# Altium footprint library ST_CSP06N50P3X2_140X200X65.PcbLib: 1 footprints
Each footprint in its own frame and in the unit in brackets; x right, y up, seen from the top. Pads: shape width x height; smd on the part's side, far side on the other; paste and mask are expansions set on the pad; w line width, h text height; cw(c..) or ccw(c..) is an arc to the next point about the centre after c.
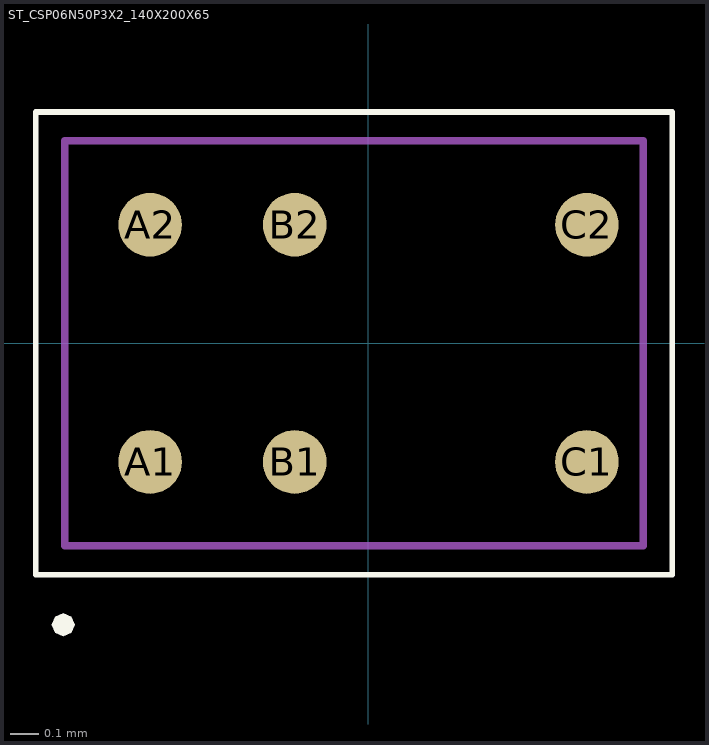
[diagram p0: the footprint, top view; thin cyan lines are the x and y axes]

## ST_CSP06N50P3X2_140X200X65 [mm] "ST_CSP06N50P3X2_140X200X65"
pads (6):
  round 0.22 smd mask+0.05: A1(-0.755,-0.41) A2(-0.755,0.41) B1(-0.255,-0.41) B2(-0.255,0.41) C1(0.755,-0.41) C2(0.755,0.41)
Top Overlay:
  pour cut-out: -1.016,-0.973 -1.028,-0.945 -1.055,-0.934 -1.083,-0.945 -1.094,-0.973 -1.083,-1 -1.055,-1.012 -1.028,-1
  lines w0.02: -1.15,-0.8 -1.15,0.8 1.05,0.8 1.05,-0.8 -1.15,-0.8
Top Paste:
  rectangle: -0.865,-0.52 -0.645,-0.3
  rectangle: -0.365,-0.52 -0.145,-0.3
  rectangle: 0.645,-0.52 0.865,-0.3
  rectangle: 0.645,0.3 0.865,0.52
  rectangle: -0.365,0.3 -0.145,0.52
  rectangle: -0.865,0.3 -0.645,0.52
Mechanical 5:
  text "B1" at -0.332,-0.9 h0.07
  text "C1" at 0.718,-0.88 h0.07
  text "A1" at -0.852,-0.9 h0.07
  text "B2" at -0.352,0.86 h0.07
  text "A2" at -0.792,0.85 h0.07
  text "C2" at 0.718,0.84 h0.07
Mechanical 6:
  lines w0.025: -1.05,-0.7 0.95,-0.7 0.95,0.7 -1.05,0.7 -1.05,-0.7
Mechanical 7:
  lines w0.025: -1.05,-0.7 -1.05,0.7 0.95,0.7 0.95,-0.7 -1.05,-0.7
